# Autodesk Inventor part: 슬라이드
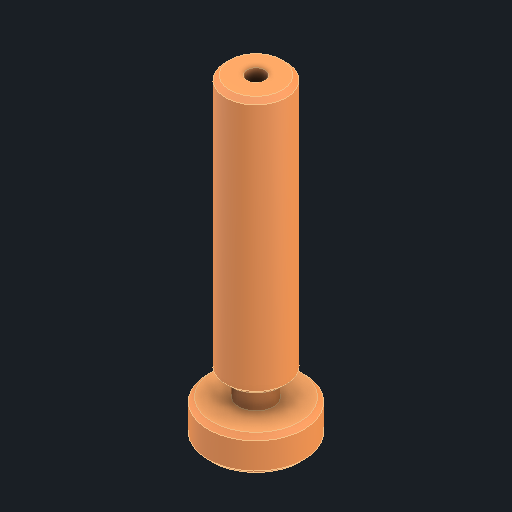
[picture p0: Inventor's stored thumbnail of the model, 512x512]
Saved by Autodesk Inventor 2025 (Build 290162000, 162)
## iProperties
Created: 2025-08
Part Number: 슬라이드
Material: 강철, 연강
Document SubType Name: Modeling
Designer: infra15
Density: 7.86 g/cm^3
Appearance: 기본값
Author: jhkim
Sending System: Autodesk Inventor 2026
Preprocessor: ST-DEVELOPER v20.1
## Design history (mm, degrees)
feature "솔리드1"
node "솔리드2"
